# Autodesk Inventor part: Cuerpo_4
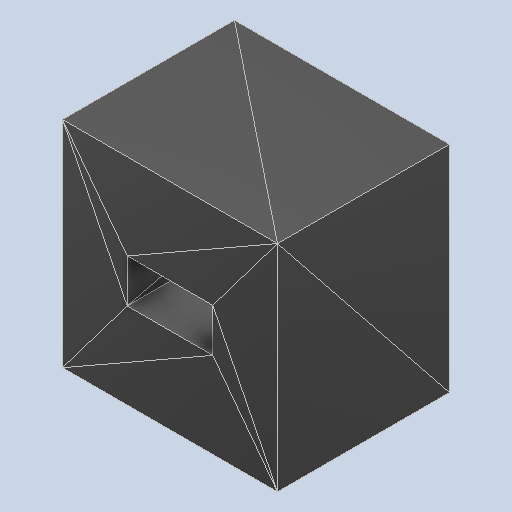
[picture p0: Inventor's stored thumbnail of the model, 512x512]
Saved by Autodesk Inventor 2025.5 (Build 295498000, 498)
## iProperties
Created: 2026-10
Part Number: Cuerpo_4
Material: Genérico
Document SubType Name: Modeling
Designer: Luis M
Density: 1 g/cm^3
Appearance: Valor por defecto
Author: Luis M
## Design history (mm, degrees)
feature "Base1"
node "Sólido1"
